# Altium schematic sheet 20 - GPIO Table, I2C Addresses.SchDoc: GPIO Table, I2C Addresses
size A3; PageSetup: Record=PageOptions¦CenterHorizontal=True¦CenterVertical=True¦PrintScale=1.01¦XCorrection=1.00¦YCorrection=1.00¦PrintKind=0¦BorderSize=5000000¦LeftOffset=0¦BottomOffset=0¦Orientation=2¦PaperLength=4200¦PaperWidth=2970¦Scale=100¦PaperSource=15¦PrintQuality=600¦MediaType=1¦DitherType=10¦PrintScaleMode=1¦PaperKind=A3¦PaperIndex=8; Author: Juan Anzola; SheetNumber: 20; SheetTotal: 21
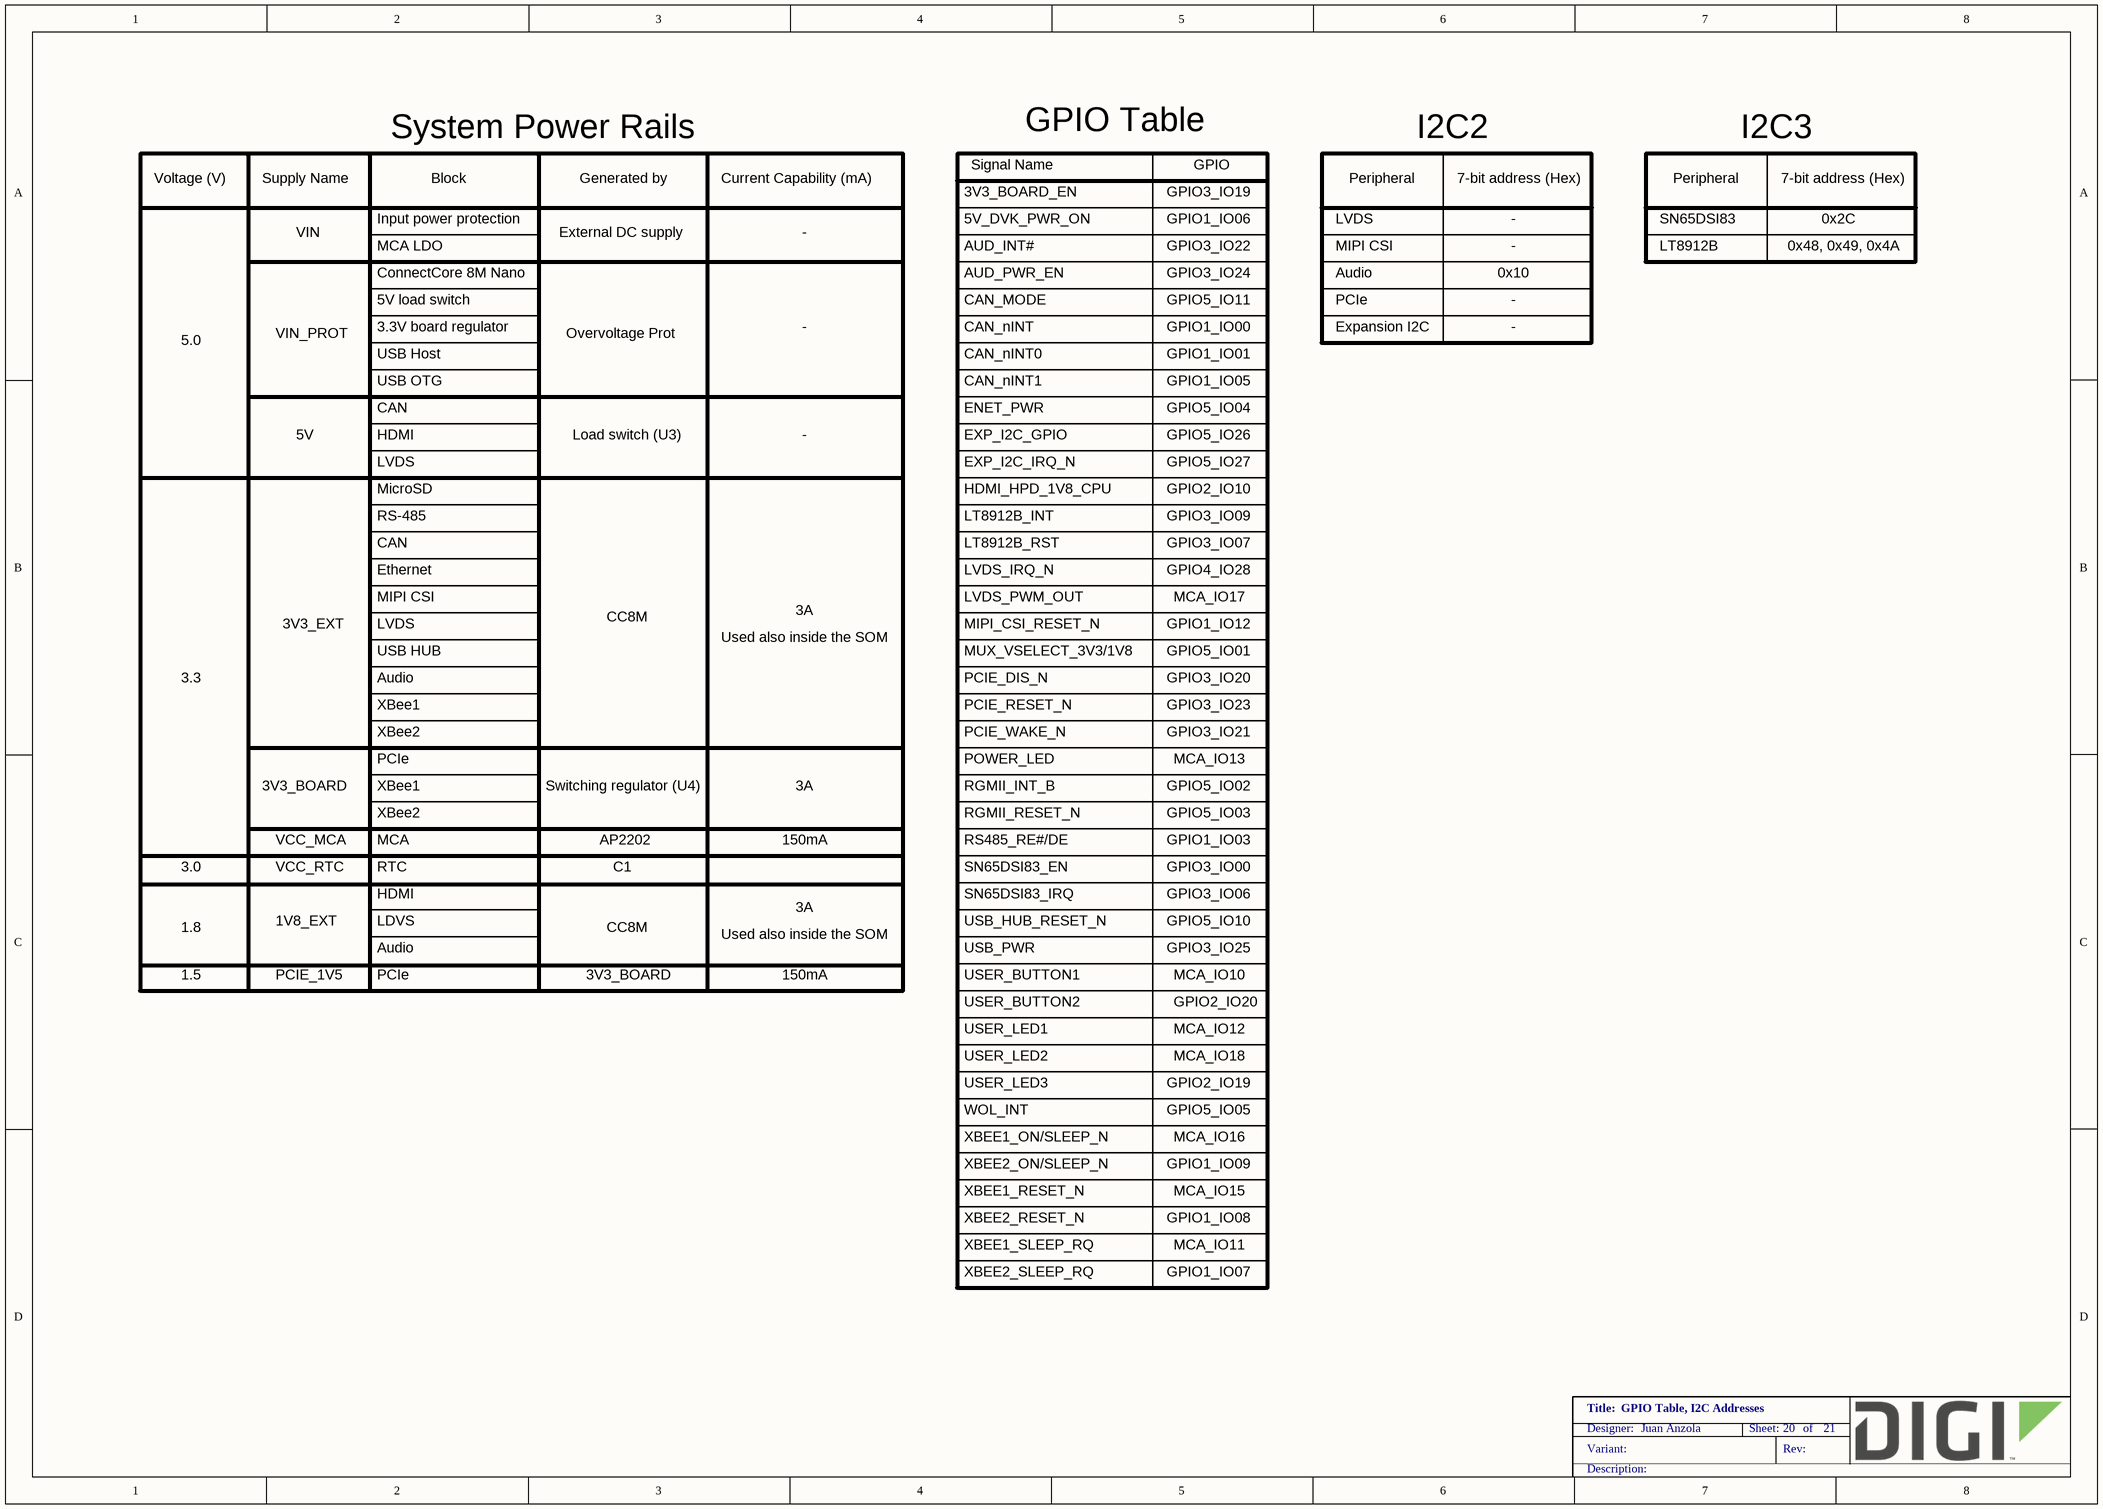
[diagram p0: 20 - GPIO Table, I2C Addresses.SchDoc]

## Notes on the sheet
- Voltage (V)
- Supply Name
- System Power Rails
- Block
- Generated by
- Current Capability (mA)
- Signal Name
- GPIO Table
- GPIO
- Peripheral
- I2C2
- 7-bit address (Hex)
- I2C3
- VIN
- Input power protection
- External DC supply
- -
- 3V3_BOARD_EN
- 5V_DVK_PWR_ON
- GPIO3_IO19
- GPIO1_IO06
- LVDS
- SN65DSI83
- 0x2C
- MCA LDO
- ConnectCore 8M Nano
- 5V load switch
- AUD_INT#
- AUD_PWR_EN
- CAN_MODE
- GPIO3_IO24
- GPIO3_IO22
- GPIO5_IO11
- PCIe
- MIPI CSI
- Audio
- 0x10
- LT8912B
- 0x48, 0x49, 0x4A
- 5.0
- VIN_PROT
- USB Host
- 3.3V board regulator
- Overvoltage Prot
- CAN_nINT
- CAN_nINT0
- GPIO1_IO00
- GPIO1_IO01
- Expansion I2C
- 5V
- HDMI
- USB OTG
- CAN
- Load switch (U3)
- CAN_nINT1
- ENET_PWR
- EXP_I2C_GPIO
- GPIO1_IO05
- GPIO5_IO04
- GPIO5_IO26
- MicroSD
- HDMI_HPD_1V8_CPU
- EXP_I2C_IRQ_N
- GPIO2_IO10
- GPIO5_IO27
- Ethernet
- RS-485
- LT8912B_RST
- LT8912B_INT
- LVDS_IRQ_N
- GPIO3_IO07
- GPIO3_IO09
- GPIO4_IO28
- 3V3_EXT
- CC8M
- Used also inside the SOM
- 3A
- LVDS_PWM_OUT
- MIPI_CSI_RESET_N
- GPIO1_IO12
- MCA_IO17
- 3.3
- USB HUB
- XBee1
- PCIE_DIS_N
- PCIE_RESET_N
- MUX_VSELECT_3V3/1V8
- GPIO3_IO23
- GPIO5_IO01
- GPIO3_IO20
- XBee2
- PCIE_WAKE_N
- POWER_LED
- GPIO3_IO21
- MCA_IO13
- 3V3_BOARD
- VCC_MCA
- MCA
- Switching regulator (U4)
- AP2202
- 150mA
- RS485_RE#/DE
- RGMII_INT_B
- RGMII_RESET_N
- GPIO1_IO03
- GPIO5_IO02
- GPIO5_IO03
- 3.0
- VCC_RTC
- RTC
- C1
- SN65DSI83_EN
- SN65DSI83_IRQ
- GPIO3_IO00
- GPIO3_IO06
- 1.8
- 1.5
- 1V8_EXT
- PCIE_1V5
- LDVS
- USB_PWR
- USER_BUTTON1
- USB_HUB_RESET_N
- GPIO3_IO25
- GPIO5_IO10
- MCA_IO10
- USER_LED1
- USER_BUTTON2
- MCA_IO12
- GPIO2_IO20
- WOL_INT
- USER_LED2
- USER_LED3
- GPIO2_IO19
- GPIO5_IO05
- MCA_IO18
- XBEE2_ON/SLEEP_N
- XBEE1_ON/SLEEP_N
- GPIO1_IO09
- MCA_IO16
- XBEE2_RESET_N
- XBEE1_SLEEP_RQ
- XBEE1_RESET_N
- GPIO1_IO08
- MCA_IO11
- MCA_IO15
- XBEE2_SLEEP_RQ
- GPIO1_IO07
